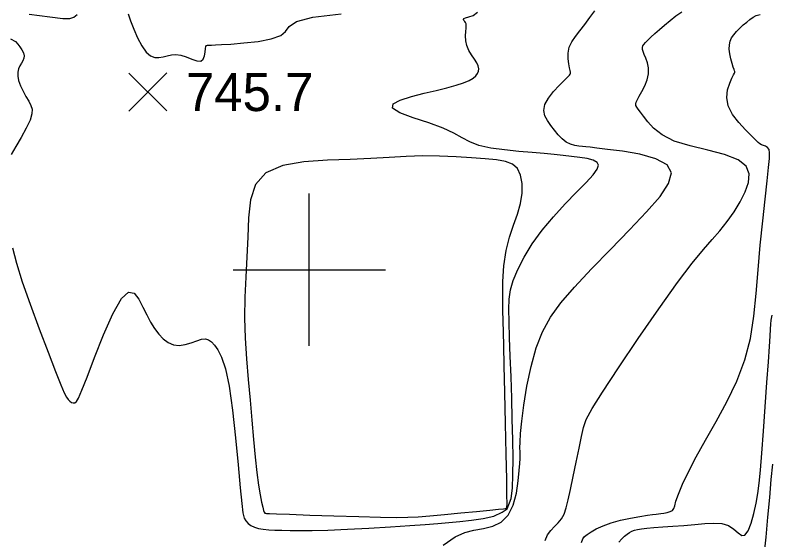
# Model space of a CAD drawing. Extents: x 2566142 to 2571431, y 418755 to 421584.
# Drawn here: x 2566884.2 to 2567182.2, y 419893.6 to 420100.3 of the extents above; entities that cross this region are included whole.
import ezdxf

# ---------------------------------------------------------------- set-up
doc = ezdxf.new("R2010")
doc.units = 0
for name, color, linetype in [('Contour_ADS_Major', 7, 'Continuous'), ('Contour_ADS_Minor', 7, 'Continuous'), ('Contour_ADS_Spot_Elevation', 7, 'Continuous'), ('Contour_ADS_Tick', 7, 'Continuous')]:
    doc.layers.add(name, color=color, linetype=linetype)

# ---------------------------------------------------------------- blocks, each defined once
blk = doc.blocks.new('S890')
at = {"layer": 'Contour_ADS_Tick'}
for p, q in [((0, -0.5), (0, 0.5)), ((-0.5, 0), (0.5, 0))]:
    blk.add_line(p, q, dxfattribs=at)
blk = doc.blocks.new('S750')
at = {"layer": 'Contour_ADS_Spot_Elevation'}
for p, q in [((-0.5, 0.498), (0.5, -0.498)), ((-0.498, -0.5), (0.498, 0.5))]:
    blk.add_line(p, q, dxfattribs=at)

msp = doc.modelspace()

# ---------------------------------------------------------------- linework, layer by layer
at = {"layer": 'Contour_ADS_Major'}
for points in [[(2567096.52, 419898.89), (2567097.99, 419900.34), (2567099.31, 419901.91), (2567100.33, 419903.79), (2567101.16, 419906.2), (2567101.95, 419909.35), (2567102.83, 419913.46), (2567103.91, 419918.6), (2567105.09, 419924.24), (2567106.22, 419929.72), (2567107.18, 419934.36), (2567107.94, 419937.83), (2567109.09, 419941.05), (2567111.36, 419945.29), (2567115.45, 419951.82), (2567121.78, 419961.42), (2567129.56, 419972.9), (2567137.69, 419984.62), (2567145.06, 419994.91), (2567150.84, 420002.52), (2567155.22, 420007.9), (2567158.67, 420011.9), (2567161.66, 420015.37), (2567164.54, 420019), (2567167.27, 420022.84), (2567169.7, 420026.75), (2567171.66, 420030.61), (2567172.96, 420034.31), (2567173.22, 420037.72), (2567171.99, 420040.76), (2567168.83, 420043.31), (2567163.55, 420045.33), (2567156.92, 420047.05), (2567149.98, 420048.74), (2567143.74, 420050.69), (2567138.98, 420053.07), (2567135.61, 420055.69), (2567133.29, 420058.25), (2567131.66, 420060.46), (2567130.44, 420062.09), (2567129.56, 420063.22), (2567128.97, 420064.03), (2567128.65, 420064.66), (2567128.57, 420065.27), (2567128.74, 420066), (2567129.2, 420066.98), (2567129.95, 420068.36), (2567130.98, 420070.2), (2567132.09, 420072.41), (2567133.05, 420074.79), (2567133.61, 420077.19), (2567133.6, 420079.46), (2567133.16, 420081.51), (2567132.52, 420083.31), (2567131.89, 420084.78), (2567131.45, 420085.92), (2567131.22, 420086.78), (2567131.2, 420087.48), (2567131.39, 420088.11), (2567131.79, 420088.76), (2567132.43, 420089.51), (2567133.34, 420090.42), (2567134.56, 420091.56), (2567136.1, 420092.98), (2567137.92, 420094.61), (2567139.94, 420096.37), (2567142.08, 420098.19), (2567144.3, 420099.98), (2567146.71, 420101.62)], [(2567092.91, 419893.32), (2567093.83, 419895.54), (2567095.07, 419897.36), (2567096.52, 419898.89)]]:
    msp.add_lwpolyline(points, dxfattribs=at)
at = {"layer": 'Contour_ADS_Minor'}
for points in [[(2566889.73, 420100.61), (2566897.93, 420099.54), (2566902.93, 420098.97), (2566905.74, 420098.94), (2566907.33, 420099.47), (2566908.59, 420100.56)], [(2566928.75, 420100.75), (2566929.69, 420098.02), (2566930.95, 420094.77), (2566932.45, 420091.34), (2566934.1, 420088.16), (2566935.82, 420085.67), (2566937.52, 420084.18)], [(2566937.52, 420084.18), (2566939.19, 420083.55), (2566940.84, 420083.52), (2566942.46, 420083.84), (2566944.08, 420084.27), (2566945.74, 420084.63), (2566947.51, 420084.77), (2566949.46, 420084.51), (2566951.6, 420083.79), (2566953.76, 420082.9), (2566955.73, 420082.22), (2566957.29, 420082.13), (2566958.29, 420082.88), (2566958.82, 420084.21), (2566959.07, 420085.74), (2566959.19, 420087.09), (2566959.35, 420087.94), (2566959.6, 420088.36), (2566960, 420088.5), (2566960.61, 420088.5), (2566961.53, 420088.49), (2566963.04, 420088.53), (2566965.47, 420088.65), (2566969.16, 420088.89), (2566974.21, 420089.3), (2566979.84, 420089.94), (2566985.04, 420090.88), (2566988.82, 420092.19), (2566990.65, 420093.88), (2566992.04, 420095.8), (2566994.97, 420097.72), (2567001.42, 420099.44), (2567012.63, 420100.84)], [(2567087.84, 420046.12), (2567082.51, 420046.58), (2567076.87, 420047.15), (2567071.47, 420047.92), (2567066.83, 420048.97), (2567063.27, 420050.34), (2567060.24, 420051.99), (2567056.98, 420053.84), (2567052.72, 420055.8), (2567047.03, 420057.81), (2567040.91, 420059.81), (2567035.71, 420061.75), (2567032.76, 420063.59), (2567033.01, 420065.28), (2567035.84, 420066.83), (2567040.27, 420068.22), (2567045.26, 420069.49), (2567049.99, 420070.62), (2567054.2, 420071.66), (2567057.81, 420072.63), (2567060.74, 420073.57), (2567062.94, 420074.5), (2567064.51, 420075.44), (2567065.57, 420076.36), (2567066.25, 420077.28), (2567066.66, 420078.2), (2567066.78, 420079.17), (2567066.57, 420080.24), (2567065.99, 420081.49), (2567065.04, 420082.94), (2567063.91, 420084.57), (2567062.82, 420086.35), (2567062, 420088.24), (2567061.62, 420090.18), (2567061.57, 420092.06), (2567061.7, 420093.76), (2567061.84, 420095.15), (2567061.85, 420096.15), (2567061.74, 420096.84), (2567061.52, 420097.33), (2567061.23, 420097.73), (2567060.92, 420098.14), (2567060.75, 420098.55), (2567060.9, 420098.92), (2567061.56, 420099.24), (2567062.84, 420099.53), (2567064.51, 420100.13), (2567066.28, 420101.45)], [(2567052.77, 419891.48), (2567057.42, 419894.74), (2567061.27, 419896.49), (2567064.85, 419897.4), (2567068.56, 419898.1), (2567072.24, 419899.04), (2567075.6, 419900.63), (2567078.37, 419903.31), (2567080.32, 419907.28), (2567081.58, 419912.02), (2567082.31, 419916.8), (2567082.71, 419920.88), (2567082.93, 419923.74), (2567083.03, 419925.63), (2567083.04, 419926.97), (2567083.01, 419928.23), (2567082.97, 419929.82), (2567083.01, 419932.13), (2567083.22, 419935.5), (2567083.7, 419940.3), (2567084.53, 419946.71), (2567085.74, 419954.16), (2567087.34, 419961.92), (2567089.34, 419969.23), (2567091.8, 419975.57), (2567094.95, 419981.29), (2567099.07, 419986.97), (2567104.42, 419993.18), (2567111.13, 420000.3), (2567118.61, 420007.98), (2567126.09, 420015.66), (2567132.83, 420022.78), (2567138.13, 420028.9), (2567141.52, 420033.98), (2567142.6, 420038.1), (2567140.96, 420041.32), (2567136.48, 420043.73), (2567130.19, 420045.46), (2567123.39, 420046.64), (2567117.4, 420047.41), (2567113.23, 420047.91), (2567110.59, 420048.22), (2567108.9, 420048.4), (2567107.58, 420048.52), (2567106.14, 420048.65), (2567104.55, 420048.91), (2567102.88, 420049.41), (2567101.21, 420050.25), (2567099.59, 420051.5), (2567098.04, 420053.1), (2567096.54, 420054.9), (2567095.11, 420056.8), (2567093.78, 420058.71), (2567092.77, 420060.66), (2567092.34, 420062.74), (2567092.76, 420065.03), (2567094.17, 420067.56), (2567096.22, 420070.14), (2567098.46, 420072.52), (2567100.41, 420074.46), (2567101.71, 420075.78), (2567102.44, 420076.57), (2567102.77, 420077.01), (2567102.87, 420077.25), (2567102.89, 420077.46), (2567102.84, 420077.8), (2567102.7, 420078.42), (2567102.47, 420079.48), (2567102.17, 420081.09), (2567101.93, 420083.11), (2567101.94, 420085.34), (2567102.38, 420087.6), (2567103.36, 420089.75), (2567104.8, 420091.87), (2567106.56, 420094.1), (2567108.51, 420096.56), (2567110.51, 420099.31), (2567112.45, 420101.99)], [(2567133.15, 419903.3), (2567135.22, 419903.6), (2567136.57, 419903.78), (2567137.55, 419903.89), (2567138.5, 419904), (2567139.67, 419904.16), (2567140.95, 419904.4), (2567142.15, 419904.74), (2567143.07, 419905.23), (2567143.58, 419905.92), (2567143.93, 419907.04), (2567144.41, 419908.85), (2567145.36, 419911.6), (2567147.01, 419915.48), (2567149.38, 419920.42), (2567152.41, 419926.28), (2567156.05, 419932.92), (2567160.16, 419940.18), (2567164.4, 419947.95), (2567168.34, 419956.09), (2567171.55, 419964.46), (2567173.74, 419972.97), (2567175.11, 419981.67), (2567176, 419990.65), (2567176.75, 420000.01), (2567177.61, 420009.69), (2567178.56, 420019.19), (2567179.49, 420027.85), (2567180.29, 420035.03), (2567180.89, 420040.25), (2567181.23, 420043.75), (2567181.28, 420045.97), (2567181.03, 420047.31), (2567180.46, 420048.15), (2567179.68, 420048.66), (2567178.85, 420048.98), (2567178.08, 420049.23), (2567177.46, 420049.56), (2567176.78, 420050.14), (2567175.76, 420051.13), (2567174.14, 420052.74), (2567171.78, 420055.06), (2567169.09, 420057.94), (2567166.62, 420061.18), (2567164.92, 420064.55), (2567164.37, 420067.84), (2567164.73, 420070.88), (2567165.56, 420073.48), (2567166.45, 420075.48), (2567167.05, 420076.76), (2567167.38, 420077.46), (2567167.51, 420077.77), (2567167.54, 420077.89), (2567167.52, 420078.01), (2567167.44, 420078.27), (2567167.27, 420078.82), (2567166.97, 420079.79), (2567166.54, 420081.27), (2567166.05, 420083.09), (2567165.64, 420085.05), (2567165.39, 420086.92), (2567165.42, 420088.55), (2567165.73, 420089.97), (2567166.31, 420091.27), (2567167.17, 420092.53), (2567168.28, 420093.83), (2567169.56, 420095.12), (2567170.92, 420096.38), (2567172.26, 420097.54), (2567173.5, 420098.56), (2567174.73, 420099.42), (2567176.03, 420100.1), (2567177.52, 420100.57)], [(2566882.4, 420090.92), (2566884.4, 420089.86), (2566885.28, 420088.83), (2566886.07, 420087.72), (2566886.84, 420086.54), (2566887.45, 420085.37), (2566887.76, 420084.26), (2566887.68, 420083.26), (2566887.27, 420082.31), (2566886.7, 420081.36), (2566886.09, 420080.33), (2566885.58, 420079.17), (2566885.26, 420077.82), (2566885.22, 420076.27), (2566885.55, 420074.48), (2566886.29, 420072.44), (2566887.33, 420070.3), (2566888.48, 420068.2), (2566889.57, 420066.32), (2566890.42, 420064.73), (2566890.9, 420063.19), (2566890.83, 420061.37), (2566890.07, 420058.96), (2566888.56, 420055.76), (2566886.57, 420052.12), (2566884.46, 420048.5), (2566882.6, 420045.37)], [(2566907.76, 419947.58), (2566908.38, 419948.05), (2566909.19, 419949.48), (2566910.48, 419952.5), (2566912.51, 419957.75), (2566915.46, 419965.47), (2566918.99, 419974.35), (2566922.68, 419982.65), (2566926.08, 419988.68), (2566928.86, 419991.18), (2566931.07, 419990.74), (2566932.89, 419988.42), (2566934.48, 419985.27), (2566936, 419982.18), (2566937.51, 419979.36), (2566939.07, 419976.83), (2566940.73, 419974.62), (2566942.54, 419972.78), (2566944.49, 419971.37), (2566946.58, 419970.48), (2566948.82, 419970.2), (2566951.18, 419970.53), (2566953.52, 419971.25), (2566955.72, 419972.05), (2566957.62, 419972.65), (2566959.13, 419972.78), (2566960.36, 419972.43), (2566961.48, 419971.6), (2566962.65, 419970.32), (2566964, 419968.49), (2566965.47, 419965.59), (2566966.99, 419961.02), (2566968.46, 419954.13), (2566969.81, 419944.68), (2566971, 419933.84), (2566972.01, 419923.15), (2566972.81, 419914.14), (2566973.42, 419907.97), (2566973.91, 419904.26), (2566974.42, 419902.2), (2566975.07, 419901.04), (2566975.94, 419900.11), (2566977.06, 419899.31), (2566978.43, 419898.65), (2566980.04, 419898.15), (2566981.91, 419897.82), (2566984.05, 419897.61), (2566986.49, 419897.49), (2566989.27, 419897.4), (2566992.45, 419897.3), (2566996.31, 419897.24), (2567001.18, 419897.27), (2567007.38, 419897.43), (2567015.03, 419897.76), (2567023.5, 419898.21), (2567031.95, 419898.72), (2567039.55, 419899.23), (2567045.69, 419899.68), (2567050.67, 419900.09), (2567055.03, 419900.48), (2567059.31, 419900.87), (2567063.87, 419901.32), (2567068.46, 419901.97), (2567072.64, 419902.99), (2567076, 419904.55), (2567077.96, 419905.88), (2567079.48, 419909.9), (2567080.06, 419914), (2567080.23, 419919.22), (2567080.24, 419925.65), (2567080.14, 419933.04), (2567079.96, 419941.08), (2567079.72, 419949.46), (2567079.45, 419957.85), (2567079.16, 419965.9), (2567078.89, 419973.24), (2567078.68, 419979.48), (2567078.56, 419984.41), (2567078.69, 419988.42), (2567079.22, 419992.04), (2567080.32, 419995.81), (2567082.12, 420000.14), (2567084.64, 420004.99), (2567087.84, 420010.17), (2567091.72, 420015.52), (2567096.17, 420020.84), (2567100.83, 420025.93), (2567105.27, 420030.53), (2567109.03, 420034.4), (2567111.76, 420037.39), (2567113.39, 420039.59), (2567113.94, 420041.17), (2567113.4, 420042.29), (2567111.84, 420043.12), (2567109.46, 420043.74), (2567106.54, 420044.2), (2567103.32, 420044.59), (2567100, 420044.96), (2567096.45, 420045.33), (2567092.46, 420045.71), (2567087.84, 420046.12)], [(2566883.11, 420008.6), (2566884.69, 420002.61), (2566887.02, 419995.27), (2566890.15, 419986.37), (2566893.7, 419976.75), (2566897.2, 419967.56), (2566900.16, 419959.94), (2566902.22, 419954.72), (2566903.54, 419951.56), (2566904.38, 419949.84), (2566905.03, 419948.9), (2566905.7, 419948.23), (2566906.4, 419947.76), (2566907.11, 419947.53), (2566907.76, 419947.58)], [(2567121.89, 419892.73), (2567123.03, 419893.97), (2567124.16, 419895.02), (2567125.15, 419895.85), (2567126.07, 419896.49), (2567127, 419896.98), (2567128.03, 419897.37), (2567129.26, 419897.69), (2567130.83, 419897.98), (2567132.92, 419898.23), (2567135.67, 419898.48), (2567139.18, 419898.74), (2567143.22, 419899.01), (2567147.51, 419899.31), (2567151.76, 419899.65), (2567155.71, 419900.01), (2567159.28, 419900.21), (2567162.41, 419900.04), (2567165.04, 419899.28), (2567167.15, 419897.88), (2567168.85, 419896.33), (2567170.27, 419895.3), (2567171.55, 419895.44), (2567172.8, 419897.2), (2567173.98, 419900.24), (2567175.05, 419904.02), (2567175.94, 419908), (2567176.61, 419911.84), (2567177.15, 419915.99), (2567177.64, 419921.08), (2567178.18, 419927.76), (2567178.83, 419936.37), (2567179.54, 419946.03), (2567180.22, 419955.56), (2567180.79, 419963.78), (2567181.19, 419969.79), (2567181.45, 419973.86), (2567181.62, 419976.58), (2567181.74, 419978.5), (2567181.9, 419980.17), (2567182.27, 419982.09)], [(2567176.14, 419872.6), (2567176.99, 419873.79), (2567177.7, 419876.64), (2567178.36, 419881.19), (2567179.09, 419887.39), (2567179.85, 419894.72), (2567180.6, 419902.57), (2567181.29, 419910.33), (2567181.91, 419917.43), (2567182.59, 419923.45)], [(2567107.23, 419892.53), (2567107.69, 419894), (2567108.37, 419894.91), (2567109.43, 419895.7), (2567110.97, 419896.71), (2567113.04, 419897.9), (2567115.67, 419899.15), (2567118.86, 419900.33), (2567122.58, 419901.35), (2567126.48, 419902.18), (2567130.14, 419902.83), (2567133.15, 419903.3)]]:
    msp.add_lwpolyline(points, dxfattribs=at)
msp.add_lwpolyline([(2567083.22, 420026.08), (2567083.87, 420030.12), (2567083.88, 420033.91), (2567083.24, 420037.22), (2567081.95, 420039.83), (2567079.99, 420041.58), (2567077.29, 420042.64), (2567073.75, 420043.27), (2567069.31, 420043.69), (2567063.93, 420044.12), (2567057.85, 420044.51), (2567051.35, 420044.77), (2567044.73, 420044.82), (2567038.18, 420044.61), (2567031.45, 420044.21), (2567024.23, 420043.76), (2567016.17, 420043.38), (2567007.15, 420043.09), (2566997.94, 420042.47), (2566989.55, 420040.99), (2566982.96, 420038.14), (2566978.88, 420033.54), (2566976.83, 420027.49), (2566976.05, 420020.43), (2566975.79, 420012.82), (2566975.44, 420005.02), (2566974.99, 419997.12), (2566974.63, 419989.14), (2566974.5, 419981.09), (2566974.74, 419972.98), (2566975.26, 419964.85), (2566975.95, 419956.73), (2566976.71, 419948.66), (2566977.44, 419940.71), (2566978.12, 419933.13), (2566978.78, 419926.17), (2566979.42, 419920.13), (2566980.06, 419915.2), (2566980.67, 419911.34), (2566981.22, 419908.46), (2566981.69, 419906.44), (2566982.04, 419905.17), (2566982.32, 419904.47), (2566982.55, 419904.16), (2566982.78, 419904.06), (2566983.17, 419904.01), (2566984.36, 419903.95), (2566987.14, 419903.85), (2566992.28, 419903.67), (2567000.18, 419903.39), (2567009.75, 419903.07), (2567019.53, 419902.76), (2567028.06, 419902.53), (2567034.29, 419902.44), (2567038.89, 419902.49), (2567042.91, 419902.71), (2567047.43, 419903.09), (2567053.2, 419903.62), (2567059.66, 419904.24), (2567065.92, 419904.84), (2567071.09, 419905.35), (2567074.51, 419905.68), (2567076.44, 419905.89), (2567077.33, 419906.02), (2567077.67, 419906.14), (2567077.83, 419906.47), (2567077.9, 419907.83), (2567077.87, 419911.2), (2567077.76, 419917.56), (2567077.55, 419927.42), (2567077.3, 419939.4), (2567077.02, 419951.63), (2567076.78, 419962.28), (2567076.58, 419969.98), (2567076.44, 419975.4), (2567076.33, 419979.71), (2567076.25, 419984.06), (2567076.2, 419989.34), (2567076.29, 419995.34), (2567076.68, 420001.57), (2567077.5, 420007.54), (2567078.83, 420012.85), (2567080.42, 420017.59), (2567081.99, 420021.94), (2567083.22, 420026.08)], close=True, dxfattribs=at)

# ---------------------------------------------------------------- block references
at = {"layer": 'Contour_ADS_Spot_Elevation', "xscale": 15, "yscale": 15}
msp.add_blockref('S750', (2566936.45, 420069.98), dxfattribs=at)
at = {"layer": 'Contour_ADS_Tick', "xscale": 60, "yscale": 60}
msp.add_blockref('S890', (2567000, 420000), dxfattribs=at)

# ---------------------------------------------------------------- texts
at = {"layer": 'Contour_ADS_Spot_Elevation'}
msp.add_text('745.7', height=15, dxfattribs=at).set_placement((2566951.45, 420062.48))

doc.saveas('drawing.dxf')
